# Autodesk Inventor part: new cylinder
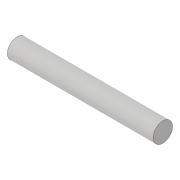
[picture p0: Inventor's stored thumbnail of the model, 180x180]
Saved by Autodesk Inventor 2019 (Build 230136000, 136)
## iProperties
Created: 2020-02
Part Number: new cylinder
Material: Generic
Document SubType Name: Modeling
Designer: Krupashree
Density: 1 g/cm^3
Appearance: Default
Author: Krupashree
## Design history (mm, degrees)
sketch "Sketch1"
  geometry: C1 r 5 at (0, 0); 1 further point
  constraints: 1 centre point, 1 coincident
  dimensions: "d0" = 10 diameter of C1
extrude "Extrusion1" new body sketch "Sketch1" distance "d1" = 75; taper "d2" = 0 deg
body "Solid1"
